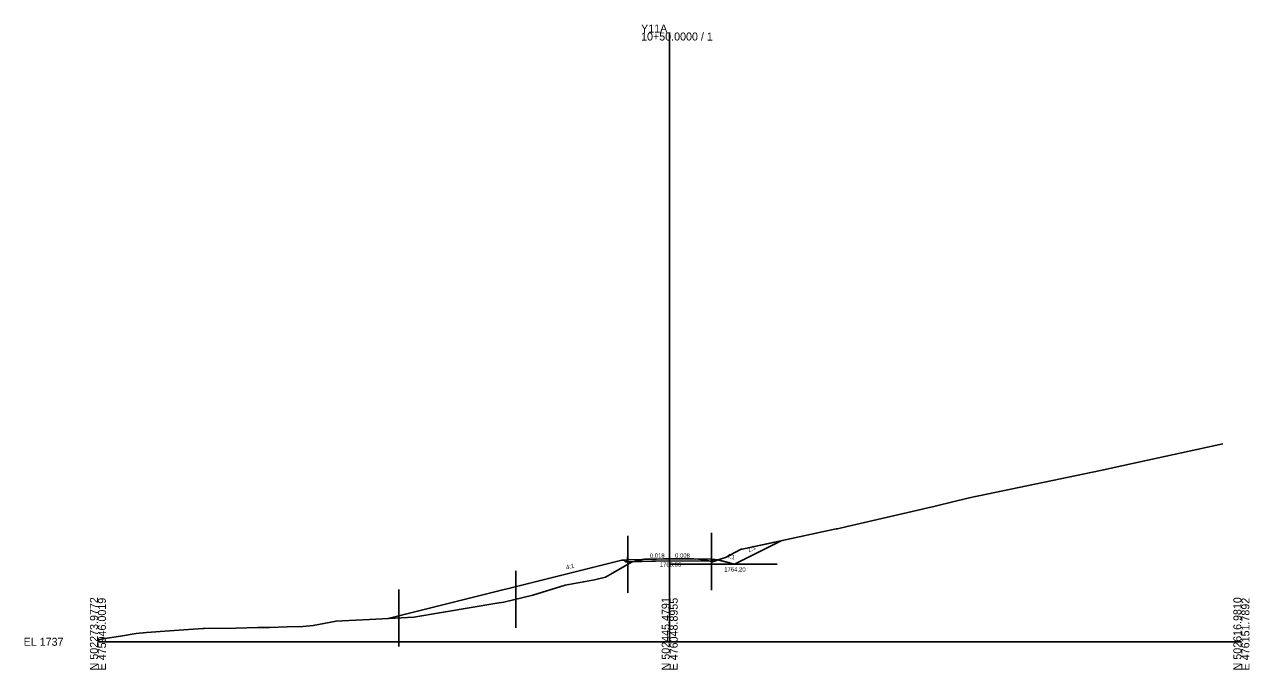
# Model space of a CAD drawing. Extents: x -26 to 403, y -10 to 5098.
# Drawn here: x -25.7 to 402.8, y 490.3 to 716 of the extents above; entities that cross this region are included whole.
import ezdxf

# ---------------------------------------------------------------- set-up
doc = ezdxf.new("R2010")
doc.units = 0
for name, color, linetype in [('Exist Cross Section Cell', 7, 'Continuous'), ('Exist XS Center Line Elevation Label', 7, 'Continuous'), ('Exist XS Ground Line', 7, 'Continuous'), ('Prop XS Ditch Slope Text', 7, 'Continuous'), ('Prop XS Ditch Standard Text', 7, 'Continuous'), ('Prop XS Dump Level', 7, 'Continuous'), ('Prop XS Earthwork Shape', 7, 'Continuous'), ('Prop XS EOT Tick Mark', 7, 'Continuous'), ('Prop XS Finish Grade', 7, 'Continuous'), ('Prop XS Finish Grade Earthwork', 7, 'Continuous'), ('Prop XS Finish Grade Pavement', 7, 'Continuous'), ('Prop XS Pvmt Edge Slope', 7, 'Continuous'), ('Prop XS SE Text', 7, 'Continuous'), ('Prop XS Shoulder Borrow Shape', 7, 'Continuous'), ('Prop XS Side Slope Text', 7, 'Continuous'), ('Prop XS Subgrade Earthwork', 7, 'Continuous'), ('Scratch_Level_5', 7, 'Continuous')]:
    doc.layers.add(name, color=color, linetype=linetype)

msp = doc.modelspace()

# ---------------------------------------------------------------- linework, layer by layer
at = {"layer": 'Exist Cross Section Cell'}
for p, q in [((200, 500), (200, 713.16)), ((0, 500), (200, 500)), ((200, 500), (400, 500))]:
    msp.add_line(p, q, dxfattribs=at)
at = {"layer": 'Exist XS Ground Line'}
msp.add_lwpolyline([(0, 500.6), (0.35, 500.67), (1.68, 501.04), (7.88, 502), (13.34, 502.9), (16.98, 503.31), (25.01, 503.85), (36.67, 504.63), (37.04, 504.63), (48.33, 504.81), (55.86, 504.97), (60, 504.97), (66.2, 505.19), (71.66, 505.3), (75.3, 505.7), (83.32, 507.24), (85.46, 507.39), (95.05, 507.75), (110.49, 508.63), (139.57, 513.48), (141.98, 513.84), (152.17, 516.37), (163.5, 519.87), (169.82, 521.01), (173.7, 521.66), (177.61, 522.66), (179.95, 524.04), (186.6, 527.82), (188.51, 528.3), (191.22, 528.86), (197.91, 529.01), (199.48, 529.07), (200, 529.06), (208.4, 528.97), (210.13, 528.95), (212.65, 528.53), (215.03, 527.98), (218.33, 529.11), (219.54, 529.53), (221.03, 530.29), (224.97, 532.36), (225.38, 532.43), (258.27, 539.47), (258.72, 539.57), (262.1, 540.34), (287.9, 546.3), (289.24, 546.61), (291.96, 547.26), (300.42, 549.26), (305.3, 550.47), (306.37, 550.71), (308.16, 551.08), (350.71, 559.87), (361.93, 562.4), (393.53, 569.26)], dxfattribs=at)
at = {"layer": 'Prop XS Dump Level'}
for p, q in [((200, 528.99), (191, 528.83)), ((209, 528.92), (200, 528.99))]:
    msp.add_line(p, q, dxfattribs=at)
at = {"layer": 'Prop XS Earthwork Shape'}
for points in [[(216.94, 528.64), (222.68, 527.2), (238.95, 535.34), (225.38, 532.43), (224.97, 532.36), (221.03, 530.29), (219.54, 529.53), (218.33, 529.11)], [(184.57, 528), (183.95, 528.61), (183.29, 528.56), (101.51, 508.12), (110.49, 508.63), (139.57, 513.48), (141.98, 513.84), (152.17, 516.37), (163.5, 519.87), (169.82, 521.01), (173.7, 521.66), (177.61, 522.66), (179.95, 524.04), (186.6, 527.82), (187.53, 528.06), (185.37, 528.02)], [(200, 528.29), (187.53, 528.06), (188.51, 528.3), (191.22, 528.86), (197.91, 529.01), (199.48, 529.07), (200, 529.06), (208.4, 528.97), (210.13, 528.95), (212.65, 528.53), (214.24, 528.17)], [(214.63, 528.16), (215.36, 528.15), (215.97, 528.76), (216.63, 528.71), (216.94, 528.64), (215.03, 527.98), (214.24, 528.17)]]:
    msp.add_lwpolyline(points, close=True, dxfattribs=at)
at = {"layer": 'Prop XS EOT Tick Mark'}
for p, q in [((185.29, 528.72), (185.29, 529.72)), ((214.63, 528.87), (214.63, 529.87))]:
    msp.add_line(p, q, dxfattribs=at)
at = {"layer": 'Prop XS Finish Grade'}
for p, q in [((185.29, 528.72), (183.95, 528.61)), ((214.63, 528.87), (215.97, 528.76))]:
    msp.add_line(p, q, dxfattribs=at)
at = {"layer": 'Prop XS Finish Grade Earthwork'}
for p, q in [((222.68, 527.2), (238.95, 535.34)), ((183.29, 528.56), (101.51, 508.12)), ((183.95, 528.61), (183.29, 528.56)), ((215.97, 528.76), (216.63, 528.71)), ((216.63, 528.71), (222.68, 527.2))]:
    msp.add_line(p, q, dxfattribs=at)
at = {"layer": 'Prop XS Finish Grade Pavement'}
for p, q in [((185.37, 528.73), (200, 528.99)), ((200, 528.99), (214.63, 528.87))]:
    msp.add_line(p, q, dxfattribs=at)
at = {"layer": 'Prop XS Pvmt Edge Slope'}
for p, q in [((185.29, 528.72), (184.57, 528)), ((214.63, 528.87), (215.36, 528.15))]:
    msp.add_line(p, q, dxfattribs=at)
at = {"layer": 'Prop XS Shoulder Borrow Shape'}
for points in [[(185.29, 528.72), (184.57, 528), (183.95, 528.61)], [(215.36, 528.15), (215.97, 528.76), (214.63, 528.87)]]:
    msp.add_lwpolyline(points, close=True, dxfattribs=at)
at = {"layer": 'Prop XS Subgrade Earthwork'}
for p, q in [((184.57, 528), (183.95, 528.61)), ((185.37, 528.02), (184.57, 528)), ((200, 528.29), (185.37, 528.02)), ((214.63, 528.16), (200, 528.29)), ((214.63, 528.16), (215.36, 528.15)), ((215.36, 528.15), (215.97, 528.76))]:
    msp.add_line(p, q, dxfattribs=at)
at = {"layer": 'Scratch_Level_5'}
for p, q in [((185.37, 537.12), (185.37, 517.12)), ((214.63, 538.07), (214.63, 518.07)), ((183.29, 528.56), (101.51, 508.12)), ((200, 527.2), (237.62, 527.2)), ((227.29, 527.15), (219.45, 527.15)), ((146.15, 524.87), (146.15, 504.87)), ((105.28, 518.33), (105.28, 498.33))]:
    msp.add_line(p, q, dxfattribs=at)

# ---------------------------------------------------------------- texts
at = {"layer": 'Exist Cross Section Cell'}
for s, p in [('Y11A', (190, 713.16)), ('10+50.0000 / 1', (190, 710.36)), ('EL 1737', (-26, 498.6))]:
    msp.add_text(s, height=2.8, dxfattribs=at).set_placement(p)
for s, p in [('N 502273.9772', (0, 490)), ('E 475946.0019', (2.8, 490)), ('N 502445.4791', (200, 490)), ('E 476048.8955', (202.8, 490)), ('N 502616.9810', (400, 490)), ('E 476151.7892', (402.8, 490))]:
    msp.add_text(s, height=2.8, rotation=90, dxfattribs=at).set_placement(p)
at = {"layer": 'Exist XS Center Line Elevation Label'}
msp.add_text('1766.06', height=1.5, dxfattribs=at).set_placement((196.53, 526.31))
at = {"layer": 'Prop XS Ditch Slope Text'}
msp.add_text('4:1', height=1.5, rotation=345.9638, dxfattribs=at).set_placement((219.84, 529.46))
at = {"layer": 'Prop XS Ditch Standard Text'}
msp.add_text('1764.20', height=1.5, dxfattribs=at).set_placement((219.09, 524.59))
at = {"layer": 'Prop XS Dump Level'}
for p in [(183.29, 528.52), (216.63, 528.67)]:
    msp.add_text('Case1', height=0.04, dxfattribs=at).set_placement(p)
at = {"layer": 'Prop XS SE Text'}
for s, rotation, p in [('0.018', 1.0503, (193.07, 529.37)), ('0.008', 359.5225, (201.89, 529.48))]:
    msp.add_text(s, height=1.5, rotation=rotation, dxfattribs=at).set_placement(p)
at = {"layer": 'Prop XS Side Slope Text'}
for s, rotation, p in [('2:1', 26.5651, (227.69, 531.24)), ('4:1', 14.0362, (163.94, 525.27))]:
    msp.add_text(s, height=1.5, rotation=rotation, dxfattribs=at).set_placement(p)

doc.saveas('drawing.dxf')
